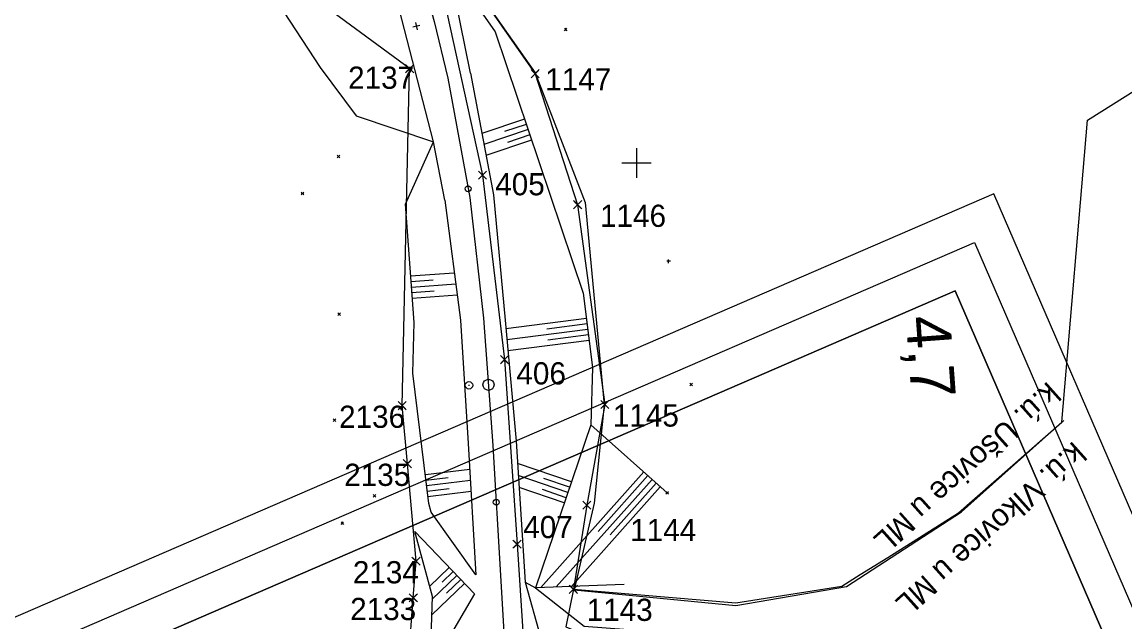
# Model space of a CAD drawing. Extents: x -866402 to -860377, y -1041908 to -1038598.
# Drawn here: x -865083.1 to -864934, y -1040462.1 to -1040381 of the extents above; entities that cross this region are included whole.
import ezdxf

# ---------------------------------------------------------------- set-up
doc = ezdxf.new("R2010")
doc.units = 0
for name, color, linetype in [('PS 02 trasa', 7, 'Continuous'), ('SZDC', 7, 'Continuous'), ('Vrstva 1', 7, 'Continuous'), ('Vrstva 48', 7, 'Continuous'), ('Vrstva 49', 7, 'Continuous'), ('Vrstva 5', 7, 'Continuous'), ('Vrstva 55', 7, 'Continuous'), ('Vrstva 60', 7, 'Continuous'), ('Vrstva 7', 7, 'Continuous')]:
    doc.layers.add(name, color=color, linetype=linetype)

msp = doc.modelspace()

# ---------------------------------------------------------------- linework, layer by layer
at = {"layer": 'PS 02 trasa'}
msp.add_lwpolyline([(-865026.39, -1040376.13), (-865020.81, -1040401.67), (-865017.86, -1040426.6), (-865016.15, -1040451.54), (-865014.56, -1040475.81), (-865012.85, -1040501.69), (-865012.38, -1040512.38), (-865012.4, -1040520.96), (-865011.76, -1040526.76), (-865011.37, -1040535.59), (-865010.07, -1040552.61), (-865007.3, -1040595.54)], dxfattribs=at)
at = {"layer": 'SZDC'}
for points in [[(-865021.96, -1040699.19), (-865027.17, -1040689.14), (-865033.06, -1040677.77), (-865026.63, -1040662), (-865024.65, -1040657.16), (-865013.46, -1040629.71), (-865015.64, -1040623.59), (-865021.21, -1040607.98), (-865022.97, -1040591.4), (-865024.6, -1040576.14), (-865021.44, -1040540.27), (-865028.84, -1040510.93), (-865030.49, -1040504.38), (-865038.28, -1040504.83), (-865037.32, -1040476.6), (-865030.76, -1040466.82), (-865030.18, -1040458.81), (-865029.81, -1040453.84), (-865030.98, -1040440.67), (-865031.68, -1040432.82), (-865030.67, -1040387.26), (-865059.89, -1040365.76)], [(-865022.71, -1040375.04), (-865013.7, -1040387.94), (-865007.96, -1040405.65), (-865004.28, -1040432.65), (-865006.72, -1040446.26), (-865008.54, -1040457.65), (-865009.56, -1040462.7), (-864989.06, -1040471.31), (-864982.51, -1040497.57), (-865001.4, -1040539.96), (-864993.69, -1040579.2), (-864996.5, -1040608.86), (-865002.06, -1040629.39), (-864985.69, -1040660.42), (-864988.74, -1040690.93)]]:
    msp.add_lwpolyline(points, dxfattribs=at)
at = {"layer": 'Vrstva 1'}
for points in [[(-865165.29, -1040225.16), (-865151.24, -1040232.21), (-865137.86, -1040239.33), (-865124.26, -1040247.44), (-865111.59, -1040256.18), (-865108.33, -1040258.65), (-865096.07, -1040268.77), (-865084.94, -1040279.3), (-865079.02, -1040285.51), (-865069.15, -1040297.13), (-865059.64, -1040310.07), (-865051.42, -1040323.06), (-865045.86, -1040333.01), (-865041.97, -1040340.79), (-865040.53, -1040343.87), (-865033.95, -1040359.82), (-865028.88, -1040375.34), (-865027.36, -1040380.88), (-865025.53, -1040388.56), (-865022.55, -1040404.7), (-865020.67, -1040420.97), (-865019.42, -1040438.2), (-865018.38, -1040455.78)], [(-865022.71, -1040375.04), (-865013.7, -1040387.94), (-865007.96, -1040405.65), (-865004.28, -1040432.65), (-865006.72, -1040446.26), (-865008.54, -1040457.65), (-864986.56, -1040459.48), (-864972.24, -1040457.22), (-864969.76, -1040455.66), (-864966.04, -1040453.33), (-864956.47, -1040447.32), (-864942.5, -1040435.03), (-864939.01, -1040394.23), (-864893.92, -1040365.81)], [(-865018.38, -1040455.78), (-865018.11, -1040460.39), (-865017.22, -1040475.75), (-865015.83, -1040499.87), (-865013.52, -1040539.81), (-865010.91, -1040584.55), (-865008.33, -1040629.67), (-865006.9, -1040655.5), (-865006.13, -1040669.15), (-865005.12, -1040685.84), (-865003.95, -1040703.11)]]:
    msp.add_lwpolyline(points, dxfattribs=at)
for points in [[(-865224.28, -1040522.07), (-864724.07, -1041678.52), (-864451.49, -1041560.62), (-864951.69, -1040404.17)], [(-864954.3, -1040410.74), (-864458.06, -1041558.01), (-864721.47, -1041671.94), (-865217.7, -1040524.67)], [(-865211.14, -1040527.28), (-864800.25, -1041477.22), (-864546.01, -1041367.26), (-864956.9, -1040417.31)], [(-864956.9, -1040417.31), (-864546.01, -1041367.26), (-864800.25, -1041477.22), (-865211.14, -1040527.28)]]:
    msp.add_lwpolyline(points, close=True, dxfattribs=at)
for centre in [(-865022.77, -1040403.5), (-865018.96, -1040445.87)]:
    msp.add_circle(centre, 0.4, dxfattribs=at)
at = {"layer": 'Vrstva 48'}
for p, q in [((-865015.14, -1040394.07), (-865020.91, -1040396.01)), ((-865014.66, -1040395.5), (-865020.63, -1040397.5)), ((-865014.9, -1040394.79), (-865017.83, -1040395.77)), ((-865014.18, -1040396.92), (-865020.35, -1040398.99)), ((-865014.42, -1040396.21), (-865017.46, -1040397.23)), ((-865030.54, -1040415.29), (-865024.64, -1040414.86)), ((-865030.48, -1040416.04), (-865027.51, -1040415.82)), ((-865030.43, -1040416.79), (-865024.44, -1040416.35)), ((-865030.37, -1040417.53), (-865027.36, -1040417.31)), ((-865030.32, -1040418.28), (-865024.24, -1040417.84)), ((-865006.78, -1040421.02), (-865017.67, -1040422.43)), ((-865006.59, -1040422.51), (-865017.53, -1040423.92)), ((-865006.69, -1040421.76), (-865012.14, -1040422.47)), ((-865006.4, -1040424), (-865017.4, -1040425.42)), ((-865006.49, -1040423.25), (-865011.98, -1040423.96)), ((-865028.55, -1040442.13), (-865022.54, -1040441.4)), ((-865008.8, -1040443.13), (-865016.09, -1040440.65)), ((-864999.02, -1040441.78), (-865012.92, -1040457.4)), ((-865028.46, -1040442.88), (-865025.48, -1040442.51)), ((-865028.37, -1040443.62), (-865022.46, -1040442.9)), ((-865009.28, -1040444.55), (-865015.99, -1040442.27)), ((-865009.04, -1040443.84), (-865012.54, -1040442.65)), ((-864997.9, -1040442.78), (-865010.85, -1040457.32)), ((-864998.46, -1040442.28), (-865005.17, -1040449.82)), ((-864997.34, -1040443.28), (-865003.58, -1040450.28)), ((-865028.28, -1040444.36), (-865025.35, -1040444.01)), ((-865028.19, -1040445.11), (-865022.37, -1040444.4)), ((-865009.76, -1040445.97), (-865015.88, -1040443.89)), ((-865009.52, -1040445.26), (-865012.73, -1040444.17)), ((-864996.78, -1040443.78), (-865008.77, -1040457.25)), ((-865025.32, -1040454.71), (-865027.98, -1040457.25)), ((-865024.8, -1040455.25), (-865026.28, -1040456.66)), ((-865023.25, -1040456.88), (-865027.68, -1040461.11)), ((-865024.28, -1040455.79), (-865027.61, -1040458.97)), ((-865023.76, -1040456.34), (-865025.71, -1040458.19))]:
    msp.add_line(p, q, dxfattribs=at)
at = {"layer": 'Vrstva 49'}
for p, q in [((-865022.44, -1040387.85), (-865025.15, -1040374.36)), ((-865009.75, -1040381.78), (-865009.4, -1040382.13)), ((-865009.75, -1040382.13), (-865009.4, -1040381.78)), ((-865022.44, -1040387.85), (-865019.35, -1040404.32)), ((-865031.24, -1040405.57), (-865027.43, -1040397.17)), ((-865025.93, -1040405.03), (-865027.43, -1040397.17)), ((-865040.45, -1040398.97), (-865040.1, -1040399.33)), ((-865040.45, -1040399.33), (-865040.1, -1040398.97)), ((-865045.34, -1040403.94), (-865044.99, -1040404.29)), ((-865045.34, -1040404.29), (-865044.99, -1040403.94)), ((-865019.35, -1040404.32), (-865017.77, -1040421.25)), ((-865025.93, -1040405.03), (-865023.79, -1040421.26)), ((-864995.41, -1040413.3), (-864995.91, -1040413.3)), ((-864995.66, -1040413.55), (-864995.66, -1040413.05)), ((-865040.39, -1040420.26), (-865040.04, -1040420.61)), ((-865040.39, -1040420.61), (-865040.04, -1040420.26)), ((-865017.77, -1040421.25), (-865016.29, -1040437.61)), ((-865023.79, -1040421.26), (-865022.74, -1040437.93)), ((-864992.8, -1040429.77), (-864992.44, -1040430.12)), ((-864992.8, -1040430.12), (-864992.44, -1040429.77)), ((-865041, -1040434.58), (-865040.65, -1040434.94)), ((-865041, -1040434.94), (-865040.65, -1040434.58)), ((-865006.18, -1040435.41), (-864995.87, -1040444.59)), ((-865022.74, -1040437.93), (-865021.73, -1040455.71)), ((-865035.62, -1040444.82), (-865035.26, -1040445.17)), ((-865035.62, -1040445.17), (-865035.26, -1040444.82)), ((-864996.05, -1040444.41), (-864995.69, -1040444.76)), ((-864996.05, -1040444.76), (-864995.69, -1040444.41)), ((-865039.95, -1040448.52), (-865039.6, -1040448.88)), ((-865039.95, -1040448.88), (-865039.6, -1040448.52)), ((-865021.91, -1040458.28), (-865029.95, -1040449.85)), ((-865015.05, -1040456.69), (-865012.94, -1040464.26)), ((-865001.67, -1040456.99), (-865013.66, -1040457.43)), ((-865021.91, -1040458.28), (-865027.91, -1040468.46))]:
    msp.add_line(p, q, dxfattribs=at)
for points in [[(-865027.43, -1040397.17), (-865032.79, -1040376.32), (-865037.61, -1040360.98), (-865043.96, -1040345.51), (-865048.42, -1040335.45)], [(-865067.91, -1040356.63), (-865054.43, -1040371.38), (-865049.34, -1040377.03), (-865042.78, -1040387.12), (-865037.88, -1040393.65), (-865027.43, -1040397.17)], [(-865025.62, -1040367.11), (-865023.95, -1040374.21), (-865022.78, -1040376.99), (-865019.09, -1040382.29)], [(-865019.09, -1040382.29), (-865007.22, -1040417.63), (-865005.93, -1040427.67), (-865006.18, -1040435.41), (-865013.66, -1040457.43)], [(-865021.73, -1040455.71), (-865027.74, -1040447.24), (-865028.08, -1040446.04), (-865030.23, -1040428.42), (-865030.08, -1040421.57), (-865031.24, -1040405.57)], [(-865016.29, -1040437.61), (-865015.05, -1040456.69), (-865013.66, -1040457.43)], [(-865027.91, -1040468.46), (-865027.6, -1040458.64), (-865029.95, -1040449.85)], [(-865013.66, -1040457.43), (-865007.09, -1040462.61), (-865001.11, -1040463.07)]]:
    msp.add_lwpolyline(points, dxfattribs=at)
at = {"layer": 'Vrstva 5'}
for p, q in [((-865000, -1040398), (-865000, -1040402)), ((-865002, -1040400), (-864998, -1040400))]:
    msp.add_line(p, q, dxfattribs=at)
at = {"layer": 'Vrstva 55'}
msp.add_line((-864956.07, -1040447.17), (-864942.25, -1040434.81), dxfattribs=at)
msp.add_lwpolyline([(-865035.78, -1040308.56), (-865029.59, -1040316.44), (-865023.71, -1040362), (-865022.71, -1040374.97), (-865013.71, -1040387.84), (-865006.92, -1040405.35), (-865004.39, -1040432.72), (-865005.73, -1040446.02), (-865008.42, -1040457.72), (-864986.56, -1040459.82), (-864971.59, -1040457.29), (-864956.07, -1040447.17)], dxfattribs=at)
at = {"layer": 'Vrstva 60'}
for p, q in [((-865030.22, -1040387.71), (-865031.22, -1040386.71)), ((-865030.22, -1040386.81), (-865031.22, -1040387.81)), ((-865031.12, -1040387.71), (-865030.12, -1040386.71)), ((-865031.12, -1040386.81), (-865030.12, -1040387.81)), ((-865030.67, -1040387.26), (-865030.67, -1040387.26)), ((-865013.25, -1040388.39), (-865014.25, -1040387.39)), ((-865013.25, -1040387.49), (-865014.25, -1040388.49)), ((-865014.15, -1040388.39), (-865013.15, -1040387.39)), ((-865014.15, -1040387.49), (-865013.15, -1040388.49)), ((-865013.7, -1040387.94), (-865013.7, -1040387.94)), ((-865020.36, -1040402.12), (-865021.36, -1040401.12)), ((-865020.36, -1040401.22), (-865021.36, -1040402.22)), ((-865021.26, -1040402.12), (-865020.26, -1040401.12)), ((-865021.26, -1040401.22), (-865020.26, -1040402.22)), ((-865020.81, -1040401.67), (-865020.81, -1040401.67)), ((-865007.51, -1040406.1), (-865008.51, -1040405.1)), ((-865007.51, -1040405.2), (-865008.51, -1040406.2)), ((-865008.41, -1040406.1), (-865007.41, -1040405.1)), ((-865008.41, -1040405.2), (-865007.41, -1040406.2)), ((-865007.96, -1040405.65), (-865007.96, -1040405.65)), ((-865017.41, -1040427.05), (-865018.41, -1040426.05)), ((-865017.41, -1040426.15), (-865018.41, -1040427.15)), ((-865018.31, -1040427.05), (-865017.31, -1040426.05)), ((-865018.31, -1040426.15), (-865017.31, -1040427.15)), ((-865017.86, -1040426.6), (-865017.86, -1040426.6)), ((-865031.23, -1040433.27), (-865032.23, -1040432.27)), ((-865031.23, -1040432.37), (-865032.23, -1040433.37)), ((-865032.13, -1040433.27), (-865031.13, -1040432.27)), ((-865032.13, -1040432.37), (-865031.13, -1040433.37)), ((-865031.68, -1040432.82), (-865031.68, -1040432.82)), ((-865003.83, -1040433.1), (-865004.83, -1040432.1)), ((-865003.83, -1040432.2), (-865004.83, -1040433.2)), ((-865004.73, -1040433.1), (-865003.73, -1040432.1)), ((-865004.73, -1040432.2), (-865003.73, -1040433.2)), ((-865004.28, -1040432.65), (-865004.28, -1040432.65)), ((-865030.53, -1040441.12), (-865031.53, -1040440.12)), ((-865030.53, -1040440.22), (-865031.53, -1040441.22)), ((-865031.43, -1040441.12), (-865030.43, -1040440.12)), ((-865031.43, -1040440.22), (-865030.43, -1040441.22)), ((-865030.98, -1040440.67), (-865030.98, -1040440.67)), ((-865006.27, -1040446.71), (-865007.27, -1040445.71)), ((-865006.27, -1040445.81), (-865007.27, -1040446.81)), ((-865007.17, -1040446.71), (-865006.17, -1040445.71)), ((-865007.17, -1040445.81), (-865006.17, -1040446.81)), ((-865006.72, -1040446.26), (-865006.72, -1040446.26)), ((-865015.7, -1040451.99), (-865016.7, -1040450.99)), ((-865016.6, -1040451.99), (-865015.6, -1040450.99)), ((-865015.7, -1040451.09), (-865016.7, -1040452.09)), ((-865016.6, -1040451.09), (-865015.6, -1040452.09)), ((-865016.15, -1040451.54), (-865016.15, -1040451.54)), ((-865029.36, -1040454.3), (-865030.36, -1040453.3)), ((-865029.36, -1040453.4), (-865030.36, -1040454.4)), ((-865030.26, -1040454.3), (-865029.26, -1040453.3)), ((-865030.26, -1040453.4), (-865029.26, -1040454.4)), ((-865029.81, -1040453.84), (-865029.81, -1040453.84)), ((-865029.73, -1040459.26), (-865030.73, -1040458.26)), ((-865029.73, -1040458.36), (-865030.73, -1040459.36)), ((-865030.63, -1040459.26), (-865029.63, -1040458.26)), ((-865030.63, -1040458.36), (-865029.63, -1040459.36)), ((-865008.09, -1040458.1), (-865009.09, -1040457.1)), ((-865008.09, -1040457.2), (-865009.09, -1040458.2)), ((-865008.99, -1040458.1), (-865007.99, -1040457.1)), ((-865008.99, -1040457.2), (-865007.99, -1040458.2)), ((-865008.54, -1040457.65), (-865008.54, -1040457.65)), ((-865030.18, -1040458.81), (-865030.18, -1040458.81))]:
    msp.add_line(p, q, dxfattribs=at)
at = {"layer": 'Vrstva 7'}
for p, q in [((-865029.28, -1040381.41), (-865030.25, -1040381.64)), ((-865029.88, -1040381.04), (-865029.65, -1040382.01)), ((-865022.7, -1040430.07), (-865022.6, -1040430.07))]:
    msp.add_line(p, q, dxfattribs=at)
for centre, radius in [((-865022.65, -1040430.07), 0.5), ((-865020.01, -1040430), 0.75)]:
    msp.add_circle(centre, radius, dxfattribs=at)

# ---------------------------------------------------------------- texts
at = {"layer": 'Vrstva 55'}
for s, p in [('k.ú. Ušovice u ML', (-864944.41, -1040429.46)), ('k.ú. Vlkovice u ML', (-864940.95, -1040437.53))]:
    msp.add_text(s, height=3, rotation=221.8127, dxfattribs=at).set_placement(p)
at = {"layer": 'Vrstva 60'}
for s, p in [('2137', (-865038.99, -1040389.98)), ('1147', (-865012.34, -1040390.2)), ('405', (-865019.1, -1040404.38)), ('1146', (-865004.93, -1040408.65)), ('406', (-865016.24, -1040429.95)), ('2136', (-865040.21, -1040435.82)), ('1145', (-865003.2, -1040435.65)), ('2135', (-865039.52, -1040443.67)), ('407', (-865015.31, -1040450.73)), ('1144', (-865000.85, -1040451.13)), ('2134', (-865038.35, -1040456.84)), ('2133', (-865038.71, -1040461.81)), ('1143', (-865006.74, -1040461.92))]:
    msp.add_text(s, height=3, dxfattribs=at).set_placement(p)
at = {"layer": 'Vrstva 7'}
msp.add_text('4,7', height=6, rotation=274.1551, dxfattribs=at).set_placement((-864963.61, -1040420.84))

doc.saveas('drawing.dxf')
